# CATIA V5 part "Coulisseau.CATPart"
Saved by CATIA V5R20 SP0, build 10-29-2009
Part number: Bitogno
Bounding box of the stored display mesh (mm): x 0 to 118, y 63.377 to 82, z 0 to 54.08
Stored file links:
  F:\IAO\Projet_IAO5.0\Coulisseau.CATPart
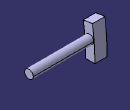
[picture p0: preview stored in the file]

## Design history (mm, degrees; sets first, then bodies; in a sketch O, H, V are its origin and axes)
Body1 (main body)
  Sketch1 on yz-plane, origin (0, 0, 0), H (0, 1, 0), V (0, 0, 1)
    arc A1 centre (-308, 0) radius 375 from (67, 0) to (63.3772, 52) ccw
    point P1 (-308, 0)
    arc A2 centre (-308, 0) radius 390 from (82, 0) to (78.2323, 54.08) ccw
    point P2 (-308, 0)
    line L1 (67, 0) -> (82, 0)
    point P3 (67, 0)
    line L2 (63.3772, 52) -> (78.2323, 54.08)
    radius A1 = 375
    radius A2 = 390
    coincidence: P1 H, P2 H, P1 P2, P3 H, L2 P2
    horizontal: L1 H
  Pad1: profile Sketch1, direction (1, 0, 0), length 20
  Sketch2 on end face of Pad1, origin (20, 0, 0), H (0, 1, 0), V (0, 0, 1)
    circle A1 centre (73.3217, 30) radius 7
    point P1 (73.3217, 30)
    reference projected line E1 (67, 0) -> (82, 0) from edge [face of Pad1 from Sketch1.L1 | end face of Pad1]
    reference projected arc E2 centre (-308, 0) radius 375 from (67, 0) to (63.3772, 52) ccw from edge [face of Pad1 from Sketch1.A1 | end face of Pad1]
    radius A1 = 7
    distance E1 P1 = 30
    distance P1 E2 = 7.5
  Pad2: profile Sketch2, direction (1, 0, 0), length 98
